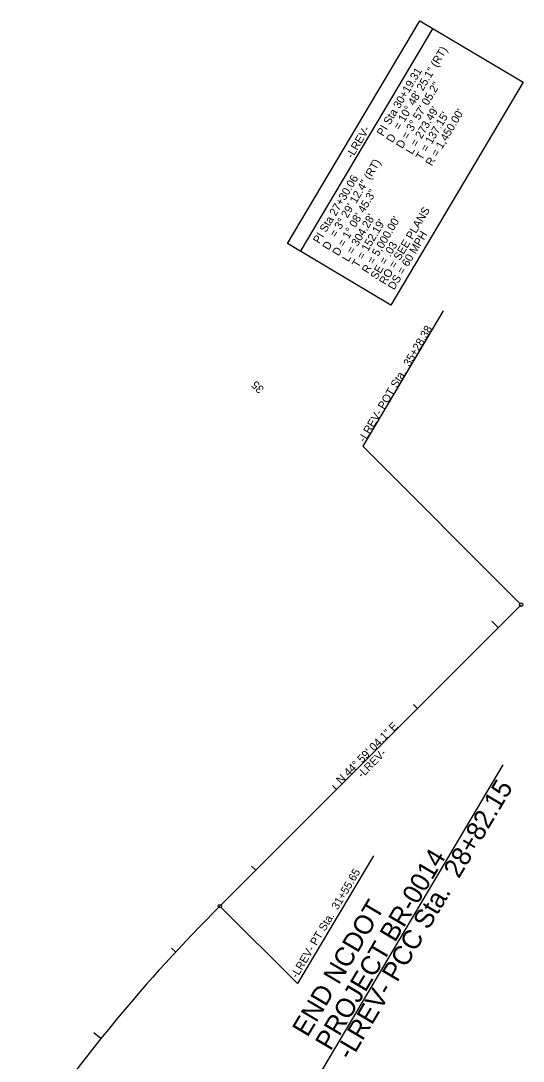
# Model space of a CAD drawing. Extents: x 2138032 to 2141863, y 405316 to 411953.
# Drawn here: x 2141424 to 2141863, y 411044 to 411953 of the extents above; entities that cross this region are included whole.
import ezdxf

# ---------------------------------------------------------------- set-up
doc = ezdxf.new("R2010")
doc.units = 0
for name, color, linetype in [('Prop Dimension', 7, 'Continuous'), ('Prop Horizontal Alignment', 7, 'Continuous'), ('Prop Horizontal Alignment Curve and Spiral Data', 7, 'Continuous'), ('Prop Horizontal Alignment Direction Label', 7, 'Continuous'), ('Prop Horizontal Alignment Station Label', 7, 'Continuous'), ('Prop Horizontal Alignment Tick Label', 7, 'Continuous'), ('Prop Horizontal Alignment Tick Large', 7, 'Continuous'), ('Prop Horizontal Alignment Tick Small', 7, 'Continuous')]:
    doc.layers.add(name, color=color, linetype=linetype)

msp = doc.modelspace()

# ---------------------------------------------------------------- linework, layer by layer
at = {"layer": 'Prop Dimension'}
msp.add_line((2141583.48, 410860.49), (2141845.93, 411302.66), dxfattribs=at)
at = {"layer": 'Prop Horizontal Alignment'}
msp.add_line((2141598.1, 411179.18), (2141861.59, 411442.81), dxfattribs=at)
msp.add_arc((2142623.69, 410154.16), 1450, 135.01552, 145.82249, dxfattribs=at)
at = {"layer": 'Prop Horizontal Alignment Curve and Spiral Data'}
msp.add_line((2141668.77, 411751.7), (2141784.41, 411946.53), dxfattribs=at)
msp.add_lwpolyline([(2141657.19, 411758.57), (2141772.83, 411953.41), (2141863.33, 411899.69), (2141747.69, 411704.86)], close=True, dxfattribs=at)
at = {"layer": 'Prop Horizontal Alignment Station Label'}
for p, q in [((2141793.33, 411699.84), (2141722.99, 411581.34)), ((2141860.53, 411443.87), (2141722.99, 411581.34)), ((2141732.33, 411223.29), (2141665.92, 411111.4)), ((2141599.16, 411178.12), (2141665.92, 411111.4))]:
    msp.add_line(p, q, dxfattribs=at)
for centre in [(2141861.59, 411442.81), (2141598.1, 411179.18)]:
    msp.add_circle(centre, 1.5, dxfattribs=at)
at = {"layer": 'Prop Horizontal Alignment Tick Large'}
for p, q in [((2141841.53, 411422.74), (2141835.87, 411428.4)), ((2141494.19, 411063.4), (2141487.95, 411068.42))]:
    msp.add_line(p, q, dxfattribs=at)
at = {"layer": 'Prop Horizontal Alignment Tick Small'}
for p, q in [((2141770.84, 411352.01), (2141767.3, 411355.55)), ((2141700.15, 411281.28), (2141696.61, 411284.82)), ((2141629.45, 411210.55), (2141625.92, 411214.09)), ((2141559.53, 411139.08), (2141555.86, 411142.47))]:
    msp.add_line(p, q, dxfattribs=at)

# ---------------------------------------------------------------- texts
at = {"layer": 'Prop Dimension'}
for s, p in [('-LREV- PCC Sta.  28+82.15', (2141712.66, 411043.62)), ('PROJECT BR-0014', (2141694.89, 411051.9)), ('END NCDOT ', (2141674.78, 411063.84))]:
    msp.add_text(s, height=16.7, rotation=59.30926, dxfattribs=at).set_placement(p)
at = {"layer": 'Prop Horizontal Alignment Curve and Spiral Data'}
for s, p in [('= 10%%d 48\' 25.1" (RT)', (2141755.36, 411857.43)), ('PI Sta 30+19.31', (2141740.8, 411851.92)), ('D = 3%%d 57\' 05.2"', (2141757.66, 411841.13)), ("L = 273.49'", (2141766.26, 411836.02)), ("T = 137.15'", (2141774.86, 411830.92)), ("R = 1,450.00'", (2141783.46, 411825.82)), ('-LREV-', (2141713.95, 411832.42)), ('D', (2141749.06, 411846.23)), ('= 3%%d 29\' 12.4" (RT)', (2141699.61, 411763.5)), ('PI Sta 27+30.06', (2141685.05, 411757.98)), ('D = 1%%d 08\' 45.3"', (2141701.9, 411747.19)), ('RO = SEE PLANS', (2141742.86, 411722)), ("L = 304.28'", (2141710.5, 411742.09)), ("R = 5,000.00'", (2141727.7, 411731.88)), ("T = 152.19'", (2141719.1, 411736.98)), ('DS = 60 MPH', (2141750.5, 411717.47)), ('D', (2141693.3, 411752.3)), ('SE = .03', (2141735.23, 411726.52))]:
    msp.add_text(s, height=7, rotation=59.30926, dxfattribs=at).set_placement(p)
at = {"layer": 'Prop Horizontal Alignment Direction Label'}
for s, p in [('N 44%%d 59\' 04.1" E', (2141704.03, 411285.46)), ('-LREV-', (2141722.49, 411290.75))]:
    msp.add_text(s, height=7, rotation=45.01552, dxfattribs=at).set_placement(p)
at = {"layer": 'Prop Horizontal Alignment Station Label'}
for s, p in [('-LREV- POT Sta.  35+28.38', (2141724.78, 411584.35)), ('-LREV- PT Sta.  31+55.65', (2141665.59, 411115.52))]:
    msp.add_text(s, height=7, rotation=59.30926, dxfattribs=at).set_placement(p)
at = {"layer": 'Prop Horizontal Alignment Tick Label'}
msp.add_text('35', height=7, rotation=135.01552, dxfattribs=at).set_placement((2141637.3, 411631.81))

doc.saveas('drawing.dxf')
